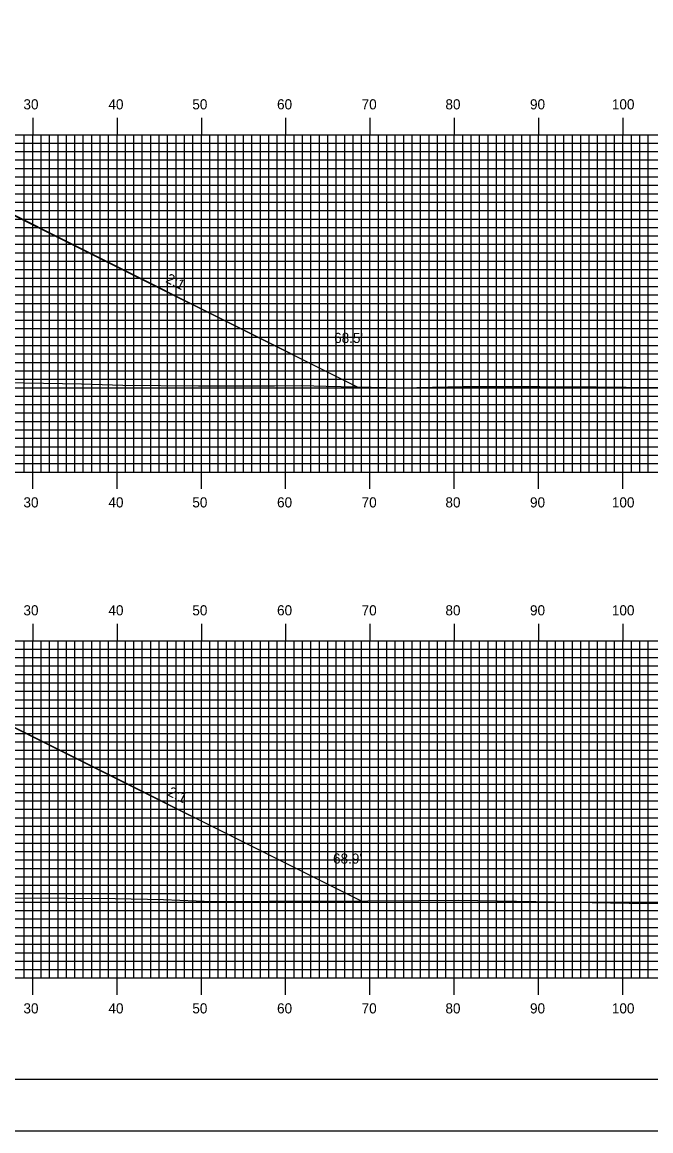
# Model space of a CAD drawing. Extents: x 1810193 to 1810536, y 442591 to 442811.
# Drawn here: x 1810387.6 to 1810462.2, y 442590.5 to 442722 of the extents above; entities that cross this region are included whole.
import ezdxf

# ---------------------------------------------------------------- set-up
doc = ezdxf.new("R2010")
doc.units = 0
for name, color, linetype in [('ANNOTATION', 7, 'Continuous'), ('BORDER', 7, 'Continuous'), ('D_Roadway_Centerline', 7, 'Continuous'), ('D_Roadway_SlopeLines', 7, 'Continuous'), ('D_Text_Standard', 7, 'Continuous'), ('H_V ANNOTATION', 7, 'Continuous'), ('MAJOR', 7, 'Continuous'), ('MINOR', 7, 'Continuous'), ('PLOT BOUNDARY', 7, 'Continuous'), ('S_Roadway_Centerline', 7, 'Continuous')]:
    doc.layers.add(name, color=color, linetype=linetype)

msp = doc.modelspace()

# ---------------------------------------------------------------- linework, layer by layer
at = {"layer": 'BORDER'}
msp.add_lwpolyline([(1810209.26, 442596.67), (1810529.26, 442596.67), (1810529.26, 442806.67), (1810209.26, 442806.67)], close=True, dxfattribs=at)
at = {"layer": 'D_Roadway_Centerline'}
for points in [[(1810288.92, 442679.5), (1810330.66, 442700.37), (1810335.86, 442702.98), (1810338.86, 442703.04), (1810346.86, 442703.2), (1810358.86, 442702.62), (1810370.86, 442702.04), (1810378.86, 442701.66), (1810381.86, 442701.52), (1810387.39, 442698.75), (1810427.35, 442678.77)], [(1810288.18, 442618.39), (1810330.66, 442639.62), (1810335.86, 442642.23), (1810338.86, 442642.29), (1810346.86, 442642.45), (1810358.86, 442641.87), (1810370.86, 442641.29), (1810378.86, 442640.91), (1810381.86, 442640.77), (1810387.39, 442638), (1810427.8, 442617.8)]]:
    msp.add_lwpolyline(points, dxfattribs=at)
at = {"layer": 'D_Roadway_SlopeLines'}
for points in [[(1810381.86, 442701.52), (1810427.35, 442678.77)], [(1810381.86, 442640.77), (1810427.8, 442617.8)]]:
    msp.add_lwpolyline(points, dxfattribs=at)
at = {"layer": 'MAJOR'}
for p, q in [((1810388.86, 442710.67), (1810388.86, 442708.67)), ((1810398.86, 442710.67), (1810398.86, 442708.67)), ((1810408.86, 442710.67), (1810408.86, 442708.67)), ((1810418.86, 442710.67), (1810418.86, 442708.67)), ((1810428.86, 442710.67), (1810428.86, 442708.67)), ((1810438.86, 442710.67), (1810438.86, 442708.67)), ((1810448.86, 442710.67), (1810448.86, 442708.67)), ((1810458.86, 442710.67), (1810458.86, 442708.67)), ((1810218.86, 442708.67), (1810498.86, 442708.67)), ((1810218.86, 442708.67), (1810498.86, 442708.67)), ((1810388.86, 442668.67), (1810388.86, 442708.67)), ((1810398.86, 442668.67), (1810398.86, 442708.67)), ((1810408.86, 442668.67), (1810408.86, 442708.67)), ((1810418.86, 442668.67), (1810418.86, 442708.67)), ((1810428.86, 442668.67), (1810428.86, 442708.67)), ((1810438.86, 442668.67), (1810438.86, 442708.67)), ((1810448.86, 442668.67), (1810448.86, 442708.67)), ((1810458.86, 442668.67), (1810458.86, 442708.67)), ((1810218.86, 442703.67), (1810498.86, 442703.67)), ((1810218.86, 442698.67), (1810498.86, 442698.67)), ((1810218.86, 442693.67), (1810498.86, 442693.67)), ((1810218.86, 442688.67), (1810498.86, 442688.67)), ((1810218.86, 442683.67), (1810498.86, 442683.67)), ((1810218.86, 442678.67), (1810498.86, 442678.67)), ((1810218.86, 442673.67), (1810498.86, 442673.67)), ((1810218.86, 442668.67), (1810498.86, 442668.67)), ((1810218.86, 442668.67), (1810498.86, 442668.67)), ((1810388.86, 442666.66), (1810388.86, 442668.67)), ((1810398.86, 442666.66), (1810398.86, 442668.67)), ((1810408.86, 442666.66), (1810408.86, 442668.67)), ((1810418.86, 442666.66), (1810418.86, 442668.67)), ((1810428.86, 442666.66), (1810428.86, 442668.67)), ((1810438.86, 442666.66), (1810438.86, 442668.67)), ((1810448.86, 442666.66), (1810448.86, 442668.67)), ((1810458.86, 442666.66), (1810458.86, 442668.67)), ((1810388.86, 442650.67), (1810388.86, 442648.67)), ((1810398.86, 442650.67), (1810398.86, 442648.67)), ((1810408.86, 442650.67), (1810408.86, 442648.67)), ((1810418.86, 442650.67), (1810418.86, 442648.67)), ((1810428.86, 442650.67), (1810428.86, 442648.67)), ((1810438.86, 442650.67), (1810438.86, 442648.67)), ((1810448.86, 442650.67), (1810448.86, 442648.67)), ((1810458.86, 442650.67), (1810458.86, 442648.67)), ((1810218.86, 442648.67), (1810498.86, 442648.67)), ((1810218.86, 442648.67), (1810498.86, 442648.67)), ((1810388.86, 442608.67), (1810388.86, 442648.67)), ((1810398.86, 442608.67), (1810398.86, 442648.67)), ((1810408.86, 442608.67), (1810408.86, 442648.67)), ((1810418.86, 442608.67), (1810418.86, 442648.67)), ((1810428.86, 442608.67), (1810428.86, 442648.67)), ((1810438.86, 442608.67), (1810438.86, 442648.67)), ((1810448.86, 442608.67), (1810448.86, 442648.67)), ((1810458.86, 442608.67), (1810458.86, 442648.67)), ((1810218.86, 442643.67), (1810498.86, 442643.67)), ((1810218.86, 442638.67), (1810498.86, 442638.67)), ((1810218.86, 442633.67), (1810498.86, 442633.67)), ((1810218.86, 442628.67), (1810498.86, 442628.67)), ((1810218.86, 442623.67), (1810498.86, 442623.67)), ((1810218.86, 442618.67), (1810498.86, 442618.67)), ((1810218.86, 442613.67), (1810498.86, 442613.67)), ((1810218.86, 442608.67), (1810498.86, 442608.67)), ((1810218.86, 442608.67), (1810498.86, 442608.67)), ((1810388.86, 442606.66), (1810388.86, 442608.67)), ((1810398.86, 442606.66), (1810398.86, 442608.67)), ((1810408.86, 442606.66), (1810408.86, 442608.67)), ((1810418.86, 442606.66), (1810418.86, 442608.67)), ((1810428.86, 442606.66), (1810428.86, 442608.67)), ((1810438.86, 442606.66), (1810438.86, 442608.67)), ((1810448.86, 442606.66), (1810448.86, 442608.67)), ((1810458.86, 442606.66), (1810458.86, 442608.67))]:
    msp.add_line(p, q, dxfattribs=at)
at = {"layer": 'MINOR'}
for p, q in [((1810387.86, 442668.67), (1810387.86, 442708.67)), ((1810389.86, 442668.67), (1810389.86, 442708.67)), ((1810390.86, 442668.67), (1810390.86, 442708.67)), ((1810391.86, 442668.67), (1810391.86, 442708.67)), ((1810392.86, 442668.67), (1810392.86, 442708.67)), ((1810393.86, 442668.67), (1810393.86, 442708.67)), ((1810394.86, 442668.67), (1810394.86, 442708.67)), ((1810395.86, 442668.67), (1810395.86, 442708.67)), ((1810396.86, 442668.67), (1810396.86, 442708.67)), ((1810397.86, 442668.67), (1810397.86, 442708.67)), ((1810399.86, 442668.67), (1810399.86, 442708.67)), ((1810400.86, 442668.67), (1810400.86, 442708.67)), ((1810401.86, 442668.67), (1810401.86, 442708.67)), ((1810402.86, 442668.67), (1810402.86, 442708.67)), ((1810403.86, 442668.67), (1810403.86, 442708.67)), ((1810404.86, 442668.67), (1810404.86, 442708.67)), ((1810405.86, 442668.67), (1810405.86, 442708.67)), ((1810406.86, 442668.67), (1810406.86, 442708.67)), ((1810407.86, 442668.67), (1810407.86, 442708.67)), ((1810409.86, 442668.67), (1810409.86, 442708.67)), ((1810410.86, 442668.67), (1810410.86, 442708.67)), ((1810411.86, 442668.67), (1810411.86, 442708.67)), ((1810412.86, 442668.67), (1810412.86, 442708.67)), ((1810413.86, 442668.67), (1810413.86, 442708.67)), ((1810414.86, 442668.67), (1810414.86, 442708.67)), ((1810415.86, 442668.67), (1810415.86, 442708.67)), ((1810416.86, 442668.67), (1810416.86, 442708.67)), ((1810417.86, 442668.67), (1810417.86, 442708.67)), ((1810419.86, 442668.67), (1810419.86, 442708.67)), ((1810420.86, 442668.67), (1810420.86, 442708.67)), ((1810421.86, 442668.67), (1810421.86, 442708.67)), ((1810422.86, 442668.67), (1810422.86, 442708.67)), ((1810423.86, 442668.67), (1810423.86, 442708.67)), ((1810424.86, 442668.67), (1810424.86, 442708.67)), ((1810425.86, 442668.67), (1810425.86, 442708.67)), ((1810426.86, 442668.67), (1810426.86, 442708.67)), ((1810427.86, 442668.67), (1810427.86, 442708.67)), ((1810429.86, 442668.67), (1810429.86, 442708.67)), ((1810430.86, 442668.67), (1810430.86, 442708.67)), ((1810431.86, 442668.67), (1810431.86, 442708.67)), ((1810432.86, 442668.67), (1810432.86, 442708.67)), ((1810433.86, 442668.67), (1810433.86, 442708.67)), ((1810434.86, 442668.67), (1810434.86, 442708.67)), ((1810435.86, 442668.67), (1810435.86, 442708.67)), ((1810436.86, 442668.67), (1810436.86, 442708.67)), ((1810437.86, 442668.67), (1810437.86, 442708.67)), ((1810439.86, 442668.67), (1810439.86, 442708.67)), ((1810440.86, 442668.67), (1810440.86, 442708.67)), ((1810441.86, 442668.67), (1810441.86, 442708.67)), ((1810442.86, 442668.67), (1810442.86, 442708.67)), ((1810443.86, 442668.67), (1810443.86, 442708.67)), ((1810444.86, 442668.67), (1810444.86, 442708.67)), ((1810445.86, 442668.67), (1810445.86, 442708.67)), ((1810446.86, 442668.67), (1810446.86, 442708.67)), ((1810447.86, 442668.67), (1810447.86, 442708.67)), ((1810449.86, 442668.67), (1810449.86, 442708.67)), ((1810450.86, 442668.67), (1810450.86, 442708.67)), ((1810451.86, 442668.67), (1810451.86, 442708.67)), ((1810452.86, 442668.67), (1810452.86, 442708.67)), ((1810453.86, 442668.67), (1810453.86, 442708.67)), ((1810454.86, 442668.67), (1810454.86, 442708.67)), ((1810455.86, 442668.67), (1810455.86, 442708.67)), ((1810456.86, 442668.67), (1810456.86, 442708.67)), ((1810457.86, 442668.67), (1810457.86, 442708.67)), ((1810459.86, 442668.67), (1810459.86, 442708.67)), ((1810460.86, 442668.67), (1810460.86, 442708.67)), ((1810461.86, 442668.67), (1810461.86, 442708.67)), ((1810218.86, 442707.67), (1810498.86, 442707.67)), ((1810218.86, 442706.67), (1810498.86, 442706.67)), ((1810218.86, 442705.67), (1810498.86, 442705.67)), ((1810218.86, 442704.67), (1810498.86, 442704.67)), ((1810218.86, 442702.67), (1810498.86, 442702.67)), ((1810218.86, 442701.67), (1810498.86, 442701.67)), ((1810218.86, 442700.67), (1810498.86, 442700.67)), ((1810218.86, 442699.67), (1810498.86, 442699.67)), ((1810218.86, 442697.67), (1810498.86, 442697.67)), ((1810218.86, 442696.67), (1810498.86, 442696.67)), ((1810218.86, 442695.67), (1810498.86, 442695.67)), ((1810218.86, 442694.67), (1810498.86, 442694.67)), ((1810218.86, 442692.67), (1810498.86, 442692.67)), ((1810218.86, 442691.67), (1810498.86, 442691.67)), ((1810218.86, 442690.67), (1810498.86, 442690.67)), ((1810218.86, 442689.67), (1810498.86, 442689.67)), ((1810218.86, 442687.67), (1810498.86, 442687.67)), ((1810218.86, 442686.67), (1810498.86, 442686.67)), ((1810218.86, 442685.67), (1810498.86, 442685.67)), ((1810218.86, 442684.67), (1810498.86, 442684.67)), ((1810218.86, 442682.67), (1810498.86, 442682.67)), ((1810218.86, 442681.67), (1810498.86, 442681.67)), ((1810218.86, 442680.67), (1810498.86, 442680.67)), ((1810218.86, 442679.67), (1810498.86, 442679.67)), ((1810218.86, 442677.67), (1810498.86, 442677.67)), ((1810218.86, 442676.67), (1810498.86, 442676.67)), ((1810218.86, 442675.67), (1810498.86, 442675.67)), ((1810218.86, 442674.67), (1810498.86, 442674.67)), ((1810218.86, 442672.67), (1810498.86, 442672.67)), ((1810218.86, 442671.67), (1810498.86, 442671.67)), ((1810218.86, 442670.67), (1810498.86, 442670.67)), ((1810218.86, 442669.67), (1810498.86, 442669.67)), ((1810218.86, 442647.67), (1810498.86, 442647.67)), ((1810387.86, 442608.67), (1810387.86, 442648.67)), ((1810389.86, 442608.67), (1810389.86, 442648.67)), ((1810390.86, 442608.67), (1810390.86, 442648.67)), ((1810391.86, 442608.67), (1810391.86, 442648.67)), ((1810392.86, 442608.67), (1810392.86, 442648.67)), ((1810393.86, 442608.67), (1810393.86, 442648.67)), ((1810394.86, 442608.67), (1810394.86, 442648.67)), ((1810395.86, 442608.67), (1810395.86, 442648.67)), ((1810396.86, 442608.67), (1810396.86, 442648.67)), ((1810397.86, 442608.67), (1810397.86, 442648.67)), ((1810399.86, 442608.67), (1810399.86, 442648.67)), ((1810400.86, 442608.67), (1810400.86, 442648.67)), ((1810401.86, 442608.67), (1810401.86, 442648.67)), ((1810402.86, 442608.67), (1810402.86, 442648.67)), ((1810403.86, 442608.67), (1810403.86, 442648.67)), ((1810404.86, 442608.67), (1810404.86, 442648.67)), ((1810405.86, 442608.67), (1810405.86, 442648.67)), ((1810406.86, 442608.67), (1810406.86, 442648.67)), ((1810407.86, 442608.67), (1810407.86, 442648.67)), ((1810409.86, 442608.67), (1810409.86, 442648.67)), ((1810410.86, 442608.67), (1810410.86, 442648.67)), ((1810411.86, 442608.67), (1810411.86, 442648.67)), ((1810412.86, 442608.67), (1810412.86, 442648.67)), ((1810413.86, 442608.67), (1810413.86, 442648.67)), ((1810414.86, 442608.67), (1810414.86, 442648.67)), ((1810415.86, 442608.67), (1810415.86, 442648.67)), ((1810416.86, 442608.67), (1810416.86, 442648.67)), ((1810417.86, 442608.67), (1810417.86, 442648.67)), ((1810419.86, 442608.67), (1810419.86, 442648.67)), ((1810420.86, 442608.67), (1810420.86, 442648.67)), ((1810421.86, 442608.67), (1810421.86, 442648.67)), ((1810422.86, 442608.67), (1810422.86, 442648.67)), ((1810423.86, 442608.67), (1810423.86, 442648.67)), ((1810424.86, 442608.67), (1810424.86, 442648.67)), ((1810425.86, 442608.67), (1810425.86, 442648.67)), ((1810426.86, 442608.67), (1810426.86, 442648.67)), ((1810427.86, 442608.67), (1810427.86, 442648.67)), ((1810429.86, 442608.67), (1810429.86, 442648.67)), ((1810430.86, 442608.67), (1810430.86, 442648.67)), ((1810431.86, 442608.67), (1810431.86, 442648.67)), ((1810432.86, 442608.67), (1810432.86, 442648.67)), ((1810433.86, 442608.67), (1810433.86, 442648.67)), ((1810434.86, 442608.67), (1810434.86, 442648.67)), ((1810435.86, 442608.67), (1810435.86, 442648.67)), ((1810436.86, 442608.67), (1810436.86, 442648.67)), ((1810437.86, 442608.67), (1810437.86, 442648.67)), ((1810439.86, 442608.67), (1810439.86, 442648.67)), ((1810440.86, 442608.67), (1810440.86, 442648.67)), ((1810441.86, 442608.67), (1810441.86, 442648.67)), ((1810442.86, 442608.67), (1810442.86, 442648.67)), ((1810443.86, 442608.67), (1810443.86, 442648.67)), ((1810444.86, 442608.67), (1810444.86, 442648.67)), ((1810445.86, 442608.67), (1810445.86, 442648.67)), ((1810446.86, 442608.67), (1810446.86, 442648.67)), ((1810447.86, 442608.67), (1810447.86, 442648.67)), ((1810449.86, 442608.67), (1810449.86, 442648.67)), ((1810450.86, 442608.67), (1810450.86, 442648.67)), ((1810451.86, 442608.67), (1810451.86, 442648.67)), ((1810452.86, 442608.67), (1810452.86, 442648.67)), ((1810453.86, 442608.67), (1810453.86, 442648.67)), ((1810454.86, 442608.67), (1810454.86, 442648.67)), ((1810455.86, 442608.67), (1810455.86, 442648.67)), ((1810456.86, 442608.67), (1810456.86, 442648.67)), ((1810457.86, 442608.67), (1810457.86, 442648.67)), ((1810459.86, 442608.67), (1810459.86, 442648.67)), ((1810460.86, 442608.67), (1810460.86, 442648.67)), ((1810461.86, 442608.67), (1810461.86, 442648.67)), ((1810218.86, 442646.67), (1810498.86, 442646.67)), ((1810218.86, 442645.67), (1810498.86, 442645.67)), ((1810218.86, 442644.67), (1810498.86, 442644.67)), ((1810218.86, 442642.67), (1810498.86, 442642.67)), ((1810218.86, 442641.67), (1810498.86, 442641.67)), ((1810218.86, 442640.67), (1810498.86, 442640.67)), ((1810218.86, 442639.67), (1810498.86, 442639.67)), ((1810218.86, 442637.67), (1810498.86, 442637.67)), ((1810218.86, 442636.67), (1810498.86, 442636.67)), ((1810218.86, 442635.67), (1810498.86, 442635.67)), ((1810218.86, 442634.67), (1810498.86, 442634.67)), ((1810218.86, 442632.67), (1810498.86, 442632.67)), ((1810218.86, 442631.67), (1810498.86, 442631.67)), ((1810218.86, 442630.67), (1810498.86, 442630.67)), ((1810218.86, 442629.67), (1810498.86, 442629.67)), ((1810218.86, 442627.67), (1810498.86, 442627.67)), ((1810218.86, 442626.67), (1810498.86, 442626.67)), ((1810218.86, 442625.67), (1810498.86, 442625.67)), ((1810218.86, 442624.67), (1810498.86, 442624.67)), ((1810218.86, 442622.67), (1810498.86, 442622.67)), ((1810218.86, 442621.67), (1810498.86, 442621.67)), ((1810218.86, 442620.67), (1810498.86, 442620.67)), ((1810218.86, 442619.67), (1810498.86, 442619.67)), ((1810218.86, 442617.67), (1810498.86, 442617.67)), ((1810218.86, 442616.67), (1810498.86, 442616.67)), ((1810218.86, 442615.67), (1810498.86, 442615.67)), ((1810218.86, 442614.67), (1810498.86, 442614.67)), ((1810218.86, 442612.67), (1810498.86, 442612.67)), ((1810218.86, 442611.67), (1810498.86, 442611.67)), ((1810218.86, 442610.67), (1810498.86, 442610.67)), ((1810218.86, 442609.67), (1810498.86, 442609.67))]:
    msp.add_line(p, q, dxfattribs=at)
at = {"layer": 'PLOT BOUNDARY'}
msp.add_lwpolyline([(1810193.08, 442590.55), (1810533.08, 442590.55), (1810533.08, 442810.55), (1810193.08, 442810.55)], close=True, dxfattribs=at)
at = {"layer": 'S_Roadway_Centerline'}
for points in [[(1810376.62, 442679.44), (1810394.66, 442679.11), (1810399.55, 442678.97), (1810408.54, 442678.88), (1810417.54, 442678.89), (1810420.74, 442678.92), (1810423.67, 442678.86), (1810432.55, 442678.64), (1810439.94, 442678.81), (1810449.02, 442678.82), (1810455.7, 442678.75), (1810462.8, 442678.71), (1810471.42, 442679.07), (1810484.46, 442680.92), (1810490.28, 442681.71), (1810496.17, 442681.64), (1810498.86, 442681.56)], [(1810380.51, 442618.21), (1810392.97, 442618.12), (1810398.64, 442618.08), (1810404.37, 442617.98), (1810410.19, 442617.74), (1810416.78, 442617.78), (1810428.61, 442617.8), (1810434.64, 442617.85), (1810439.35, 442617.9), (1810450.82, 442617.7), (1810461.79, 442617.52), (1810468.48, 442617.66), (1810474.48, 442617.44), (1810480.08, 442617.47), (1810486.51, 442617.28), (1810492.4, 442617.36), (1810498.86, 442617.49)]]:
    msp.add_lwpolyline(points, dxfattribs=at)

# ---------------------------------------------------------------- texts
at = {"layer": 'ANNOTATION'}
for p in [(1810404.54, 442691.21), (1810404.77, 442630.35)]:
    msp.add_text('2:1', height=1.2, rotation=333.4349, dxfattribs=at).set_placement(p)
at = {"layer": 'D_Text_Standard'}
for s, p in [("68.5'", (1810424.61, 442683.97)), ("68.9'", (1810424.48, 442622.23))]:
    msp.add_text(s, height=1.2, dxfattribs=at).set_placement(p)
at = {"layer": 'H_V ANNOTATION'}
for s, p in [('30', (1810387.76, 442711.67)), ('40', (1810397.84, 442711.67)), ('50', (1810407.79, 442711.67)), ('60', (1810417.84, 442711.67)), ('70', (1810427.87, 442711.67)), ('80', (1810437.81, 442711.67)), ('90', (1810447.84, 442711.67)), ('100', (1810457.55, 442711.67)), ('30', (1810387.76, 442664.47)), ('40', (1810397.84, 442664.47)), ('50', (1810407.79, 442664.47)), ('60', (1810417.84, 442664.47)), ('70', (1810427.87, 442664.47)), ('80', (1810437.81, 442664.47)), ('90', (1810447.84, 442664.47)), ('100', (1810457.55, 442664.47)), ('30', (1810387.76, 442651.67)), ('40', (1810397.84, 442651.67)), ('50', (1810407.79, 442651.67)), ('60', (1810417.84, 442651.67)), ('70', (1810427.87, 442651.67)), ('80', (1810437.81, 442651.67)), ('90', (1810447.84, 442651.67)), ('100', (1810457.55, 442651.67)), ('30', (1810387.76, 442604.47)), ('40', (1810397.84, 442604.47)), ('50', (1810407.79, 442604.47)), ('60', (1810417.84, 442604.47)), ('70', (1810427.87, 442604.47)), ('80', (1810437.81, 442604.47)), ('90', (1810447.84, 442604.47)), ('100', (1810457.55, 442604.47))]:
    msp.add_text(s, height=1.2, dxfattribs=at).set_placement(p)

doc.saveas('drawing.dxf')
